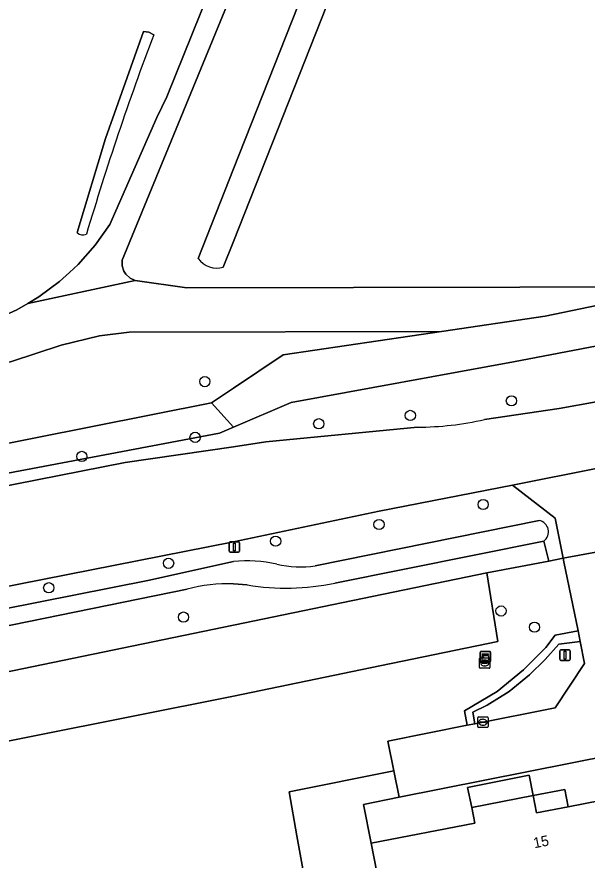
# Model space of a CAD drawing. Extents: x 160203 to 161530, y 379528 to 381797.
# Drawn here: x 160979.3 to 161033.8, y 379917 to 379997.6 of the extents above; entities that cross this region are included whole.
import ezdxf

# ---------------------------------------------------------------- set-up
doc = ezdxf.new("R2010")
doc.units = 0
for name, color, linetype in [('IMGEO_Boom', 7, 'Continuous'), ('IMGEO_Grasland_overig', 7, 'Continuous'), ('IMGEO_Groenvoorziening', 7, 'Continuous'), ('IMGEO_Hek', 7, 'Continuous'), ('IMGEO_Kast', 7, 'Continuous'), ('IMGEO_Kolk', 7, 'Continuous'), ('IMGEO_Lichtmast', 7, 'Continuous'), ('IMGEO_Loofbos', 7, 'Continuous'), ('IMGEO_Pand', 7, 'Continuous'), ('IMGEO_Pand_nummerreeks', 7, 'Continuous'), ('IMGEO_Rijbaan_lokaal_open', 7, 'Continuous'), ('IMGEO_Rioolput', 7, 'Continuous'), ('IMGEO_Voetpad_onverhard', 7, 'Continuous'), ('IMGEO_Voetpad_open', 7, 'Continuous'), ('IMGEO_Waterloop', 7, 'Continuous')]:
    doc.layers.add(name, color=color, linetype=linetype)

msp = doc.modelspace()

# ---------------------------------------------------------------- linework, layer by layer
at = {"layer": 'IMGEO_Boom'}
for centre in [(160997.258, 379962.718), (161026.554, 379960.88), (161016.895, 379959.487), (161008.142, 379958.692), (160996.323, 379957.392), (160985.503, 379955.574), (161023.86, 379950.978), (161013.905, 379949.071), (161004.021, 379947.471), (160993.789, 379945.357), (160982.341, 379943.021), (161025.562, 379940.803), (160995.214, 379940.22), (161028.765, 379939.255)]:
    msp.add_circle(centre, 0.489, dxfattribs=at)
at = {"layer": 'IMGEO_Grasland_overig'}
msp.add_lwpolyline([(161008.006, 379908.641), (161006.059, 379919.315), (161005.317, 379923.52), (161015.307, 379925.53), (161014.737, 379928.361), (161022.338, 379929.878), (161022.088, 379931.253), (161025.189, 379933.097), (161027.702, 379935.192), (161029.839, 379937.308), (161030.74, 379938.502), (161032.921, 379938.901), (161031.58, 379945.502), (161031.511, 379945.843), (161030.126, 379945.579), (161024.194, 379944.451), (161025.245, 379937.898), (161013.069, 379935.373), (161000, 379932.662), (160951.544, 379923.025), (160959.272, 379883.804)], dxfattribs=at)
at = {"layer": 'IMGEO_Groenvoorziening'}
for points in [[(161029.658, 379947.483), (161030.126, 379945.579), (161031.511, 379945.843), (161030.736, 379949.662), (161026.674, 379952.839), (161013.911, 379950.345), (161000, 379947.411), (160936.325, 379934.86), (160930.729, 379933.941), (160927.405, 379933.308)], [(161007.816, 379945.111), (161029.198, 379949.449)], [(161000, 379939.454), (161011.409, 379941.81), (161024.194, 379944.451), (161030.126, 379945.579), (161029.658, 379947.483), (161009.68, 379943.467)], [(160939.993, 379933.455), (160991.806, 379943.722), (161000, 379945.518)], [(161001.31, 379943.287), (161000, 379943.392)], [(160995.56, 379942.876), (160940.767, 379931.705), (160943.379, 379927.759), (161000, 379939.454)]]:
    msp.add_lwpolyline(points, dxfattribs=at)
for points in [[(161033.129, 379937.878), (161032.921, 379938.901), (161030.74, 379938.502), (161029.839, 379937.308), (161027.702, 379935.192), (161025.189, 379933.097), (161022.088, 379931.253), (161022.338, 379929.878), (161023.071, 379930.024), (161022.863, 379931.128), (161024.225, 379931.798), (161026.341, 379933.097), (161028.289, 379934.71), (161029.777, 379936.156), (161031.096, 379937.622)], [(161033.555, 379935.783), (161033.129, 379937.878), (161031.096, 379937.622), (161029.777, 379936.156), (161028.289, 379934.71), (161026.341, 379933.097), (161024.225, 379931.798), (161022.863, 379931.128), (161023.071, 379930.024), (161030.744, 379931.555)]]:
    msp.add_lwpolyline(points, close=True, dxfattribs=at)
for centre, radius, start, end in [((161029.003, 379948.367), 1.1, 306.54814, 79.78991), ((161001.34, 379933.014), 12.576, 77.15642, 96.11878), ((161006.447, 379955.76), 10.737, 257.57086, 277.32572), ((160999.474, 379928.555), 14.846, 87.97087, 105.28706), ((161005.018, 379965.579), 22.598, 260.55704, 281.90691)]:
    msp.add_arc(centre, radius, start, end, dxfattribs=at)
at = {"layer": 'IMGEO_Hek'}
for points in [[(161031.511, 379945.843), (161030.126, 379945.579)], [(161030.126, 379945.579), (161024.194, 379944.451)], [(161024.194, 379944.451), (161025.245, 379937.898), (161013.069, 379935.373)], [(161013.069, 379935.373), (161000, 379932.662)], [(161000, 379932.662), (160951.544, 379923.025), (160959.272, 379883.804)]]:
    msp.add_lwpolyline(points, dxfattribs=at)
at = {"layer": 'IMGEO_Kast'}
for p, q in [((161023.644, 379936.933), (161024.485, 379936.933)), ((161024.485, 379936.933), (161023.644, 379936.933)), ((161024.569, 379936.858), (161024.569, 379936.017)), ((161024.569, 379936.017), (161024.569, 379936.858)), ((161023.569, 379936.008), (161023.569, 379936.849)), ((161023.569, 379936.849), (161023.569, 379936.008)), ((161024.494, 379935.933), (161023.653, 379935.933)), ((161023.653, 379935.933), (161024.494, 379935.933))]:
    msp.add_line(p, q, dxfattribs=at)
for points in [[(161023.764, 379936.723), (161024.364, 379936.723), (161024.364, 379936.638), (161023.764, 379936.638), (161023.764, 379936.723)], [(161023.764, 379936.548), (161024.364, 379936.548), (161024.364, 379936.059), (161023.764, 379936.059), (161023.764, 379936.548)]]:
    msp.add_lwpolyline(points, dxfattribs=at)
msp.add_circle((161023.848, 379936.397), 0.0377, dxfattribs=at)
for centre, start, end in [((161023.647, 379936.855), 92.4484, 184.28452), ((161023.647, 379936.855), 92.4484, 184.28452), ((161024.491, 379936.855), 2.4484, 94.28452), ((161024.491, 379936.855), 2.4484, 94.28452), ((161023.647, 379936.011), 182.4484, 274.28452), ((161023.647, 379936.011), 182.4484, 274.28452), ((161024.491, 379936.011), 272.4484, 4.28452), ((161024.491, 379936.011), 272.4484, 4.28452)]:
    msp.add_arc(centre, 0.0779, start, end, dxfattribs=at)
at = {"layer": 'IMGEO_Kolk'}
for p, q in [((161023.337, 379929.75), (161023.337, 379930.602)), ((161023.412, 379930.676), (161024.264, 379930.676)), ((161023.825, 379930.456), (161023.85, 379930.456)), ((161024.338, 379930.602), (161024.338, 379929.75)), ((161024.264, 379929.676), (161023.412, 379929.676)), ((161023.596, 379930.17), (161023.596, 379930.182)), ((161024.034, 379930.133), (161023.636, 379930.133)), ((161023.639, 379930.219), (161024.037, 379930.219)), ((161023.848, 379929.896), (161023.823, 379929.896)), ((161024.08, 379930.182), (161024.08, 379930.17))]:
    msp.add_line(p, q, dxfattribs=at)
for points in [[(161023.337, 379929.75), (161023.337, 379930.602)], [(161023.412, 379930.676), (161024.264, 379930.676)], [(161024.338, 379930.602), (161024.338, 379929.75)], [(161024.264, 379929.676), (161023.412, 379929.676)]]:
    msp.add_lwpolyline(points, dxfattribs=at)
for centre, radius, start, end in [((161023.414, 379930.6), 0.0765, 91.55205, 178.44795), ((161023.414, 379930.6), 0.0765, 91.55205, 178.44795), ((161024.262, 379930.6), 0.0765, 1.55205, 88.44795), ((161024.262, 379930.6), 0.0765, 1.55205, 88.44795), ((161023.414, 379929.752), 0.0765, 181.55205, 268.44795), ((161023.414, 379929.752), 0.0765, 181.55205, 268.44795), ((161023.636, 379930.179), 0.0403, 85.87752, 175.75265), ((161023.633, 379930.169), 0.0366, 178.93798, 274.71019), ((161024.037, 379930.176), 0.043, 264.86636, 352.45326), ((161024.041, 379930.181), 0.0386, 1.73085, 96.63898), ((161024.262, 379929.752), 0.0765, 271.55205, 358.44795), ((161024.262, 379929.752), 0.0765, 271.55205, 358.44795)]:
    msp.add_arc(centre, radius, start, end, dxfattribs=at)
for centre, major_axis, ratio, start_param, end_param in [((161023.824, 379930.176), (-0.387, 0.002), 0.722429, 4.712389, 7.853982), ((161023.849, 379930.176), (-0.39, 0.002), 0.717154, 1.570796, 4.712389)]:
    msp.add_ellipse(centre, major_axis=major_axis, ratio=ratio, start_param=start_param, end_param=end_param, dxfattribs=at)
at = {"layer": 'IMGEO_Lichtmast'}
for p, q in [((160999.689, 379947.418), (161000.479, 379947.418)), ((161000.479, 379947.418), (160999.689, 379947.418)), ((160999.589, 379946.518), (160999.589, 379947.318)), ((160999.589, 379947.318), (160999.589, 379946.518)), ((161000.579, 379947.318), (161000.579, 379946.518)), ((161000.579, 379946.518), (161000.579, 379947.318)), ((161000.479, 379946.418), (160999.689, 379946.418)), ((160999.689, 379946.418), (161000.479, 379946.418)), ((161031.193, 379936.186), (161031.193, 379936.986)), ((161031.193, 379936.986), (161031.193, 379936.186)), ((161031.293, 379937.086), (161032.083, 379937.086)), ((161032.083, 379937.086), (161031.293, 379937.086)), ((161032.183, 379936.986), (161032.183, 379936.186)), ((161032.183, 379936.186), (161032.183, 379936.986)), ((161032.083, 379936.086), (161031.293, 379936.086)), ((161031.293, 379936.086), (161032.083, 379936.086))]:
    msp.add_line(p, q, dxfattribs=at)
for points in [[(161000.009, 379947.293), (161000.159, 379947.293), (161000.159, 379946.543), (161000.009, 379946.543), (161000.009, 379947.293)], [(161031.613, 379936.961), (161031.763, 379936.961), (161031.763, 379936.211), (161031.613, 379936.211), (161031.613, 379936.961)]]:
    msp.add_lwpolyline(points, dxfattribs=at)
for centre, start, end in [((160999.689, 379947.318), 90, 180), ((160999.689, 379947.318), 90, 180), ((161000.479, 379947.318), 0, 90), ((161000.479, 379947.318), 360, 90), ((160999.689, 379946.518), 180, 270), ((160999.689, 379946.518), 180, 270), ((161000.479, 379946.518), 270, 0), ((161000.479, 379946.518), 270, 0), ((161031.293, 379936.986), 90, 180), ((161031.293, 379936.986), 90, 180), ((161032.083, 379936.986), 0, 90), ((161032.083, 379936.986), 360, 90), ((161031.293, 379936.186), 180, 270), ((161031.293, 379936.186), 180, 270), ((161032.083, 379936.186), 270, 0), ((161032.083, 379936.186), 270, 0)]:
    msp.add_arc(centre, 0.1, start, end, dxfattribs=at)
at = {"layer": 'IMGEO_Loofbos'}
for points in [[(161052.225, 380030.051), (161019.281, 380024.896), (161017.421, 380024.586), (161017.24, 380024.558), (161016.059, 380030.822), (161013.831, 380030.846), (161014.708, 380026.37), (161016.833, 380018.757), (161009.428, 380000), (161000, 379976.12), (160999.016, 379973.646)], [(160910.327, 380007.409), (160920.602, 379955.987), (160921, 379955.813), (160922.449, 379955.516), (160923.188, 379955.482), (160935.494, 379958.213), (160972.092, 379967.237), (160974.767, 379967.81), (160977.079, 379968.582), (160979.298, 379969.591), (160980.332, 379970.199), (160981.399, 379970.826), (160983.359, 379972.274), (160984.32, 379973.153), (160985.158, 379973.92), (160986.774, 379975.744), (160988.191, 379977.727), (160992.684, 379987.962), (160993.627, 379989.939), (160997.664, 379999.984)], [(160999.915, 380000.009), (160989.365, 379974.323), (160989.363, 379973.786), (160989.527, 379973.275), (160989.721, 379972.973), (160990.119, 379972.613), (160990.608, 379972.392), (160995.525, 379971.689), (161043.296, 379971.789)], [(160996.624, 379974.475), (161000, 379983.055), (161006.691, 380000)], [(160987.767, 379985.934), (160991.408, 379996.16), (160991.919, 379996.12), (160992.366, 379995.868)], [(160985.041, 379976.957), (160987.767, 379985.934)], [(161093.454, 379977.21), (161081.741, 379975.129), (161026.757, 379964.623), (161005.514, 379960.734), (161000, 379958.372), (160998.654, 379957.795), (160935.592, 379945.881), (160935.239, 379948.227), (160922.706, 379945.785), (160921.668, 379948.198), (160919.01, 379947.114), (160919.54, 379945.851)], [(161023.99, 379959.09), (161031.108, 379960.14), (161038.188, 379961.422), (161094.262, 379972.527)], [(160926.483, 379942.53), (160935.112, 379944.265), (160989.654, 379954.98), (160999.998, 379956.482), (161003.088, 379956.98), (161017.577, 379958.366)]]:
    msp.add_lwpolyline(points, dxfattribs=at)
for points in [[(160997.906, 379960.687), (161000, 379962.09), (161004.745, 379965.268), (161019.862, 379967.505), (160990.026, 379967.436), (160987.186, 379967.088), (160983.541, 379966.218), (160978.788, 379964.646), (160970.004, 379962.58), (160935.992, 379955.526), (160925.518, 379952.646), (160924.211, 379951.846), (160923.099, 379950.792), (160922.23, 379949.53), (160921.668, 379948.198), (160922.706, 379945.785), (160935.239, 379948.227)], [(160952.452, 379881.869), (160959.428, 379883.014), (160959.272, 379883.804), (160951.544, 379923.025), (161000, 379932.662), (161013.069, 379935.373), (161025.245, 379937.898), (161024.194, 379944.451), (161011.409, 379941.81), (161000, 379939.454), (160943.379, 379927.759)]]:
    msp.add_lwpolyline(points, close=True, dxfattribs=at)
for centre, radius, start, end in [((161257.812, 379895.769), 283.692, 159.33872, 163.40228), ((160985.593, 379977.493), 0.769, 224.14196, 296.78874), ((160998.413, 379975.771), 2.209, 215.92327, 285.84697), ((161017.4, 379988.702), 30.336, 270.33511, 282.54724)]:
    msp.add_arc(centre, radius, start, end, dxfattribs=at)
at = {"layer": 'IMGEO_Pand'}
msp.add_lwpolyline([(161046.896, 379912.321), (161044.514, 379924.54), (161031.976, 379922.096), (161028.959, 379921.508), (161028.637, 379923.159), (161022.767, 379922.015), (161023.054, 379920.543), (161013.14, 379918.61), (161015.016, 379908.99), (161011.092, 379908.224), (161011.112, 379908.12), (161011.931, 379903.919), (161012.674, 379900.106), (161016.6, 379900.871), (161017.231, 379897.34), (161019.464, 379897.771), (161029.029, 379899.615), (161028.111, 379904.521), (161034.944, 379905.853), (161035.16, 379905.895), (161034.758, 379907.958), (161047.271, 379910.397)], close=True, dxfattribs=at)
at = {"layer": 'IMGEO_Rijbaan_lokaal_open'}
for points in [[(161044.221, 379956.334), (161108.127, 379968.844), (161108.111, 379969.144), (161118.172, 379970.493), (161117.701, 379976.481), (161107.96, 379975.052), (161107.822, 379975.214), (161105.071, 379974.669), (161094.262, 379972.527), (161038.188, 379961.422), (161031.108, 379960.14), (161023.99, 379959.09)], [(161017.577, 379958.366), (161003.088, 379956.98), (160999.998, 379956.482), (160989.654, 379954.98), (160935.112, 379944.265), (160926.483, 379942.53)], [(160927.405, 379933.308), (160930.729, 379933.941), (160936.325, 379934.86), (161000, 379947.411), (161013.911, 379950.345), (161026.674, 379952.839), (161034.962, 379954.474), (161044.221, 379956.334)]]:
    msp.add_lwpolyline(points, dxfattribs=at)
for points in [[(161034.962, 379954.474), (161026.674, 379952.839), (161030.736, 379949.662), (161031.511, 379945.843), (161036.526, 379946.773)], [(161037.21, 379943.405), (161036.526, 379946.773), (161031.511, 379945.843), (161031.58, 379945.502), (161032.921, 379938.901), (161033.129, 379937.878), (161033.555, 379935.783), (161030.744, 379931.555), (161023.071, 379930.024), (161022.338, 379929.878), (161014.737, 379928.361), (161015.307, 379925.53), (161015.815, 379923.004), (161040.379, 379927.872), (161038.943, 379934.911)]]:
    msp.add_lwpolyline(points, close=True, dxfattribs=at)
msp.add_arc((161017.4, 379988.702), 30.336, 270.33511, 282.54724, dxfattribs=at)
at = {"layer": 'IMGEO_Rioolput'}
for p, q in [((161023.506, 379935.404), (161023.506, 379936.256)), ((161023.581, 379936.33), (161024.433, 379936.33)), ((161023.994, 379936.11), (161024.019, 379936.11)), ((161024.507, 379936.256), (161024.507, 379935.404)), ((161024.433, 379935.33), (161023.581, 379935.33)), ((161023.765, 379935.824), (161023.765, 379935.836)), ((161024.203, 379935.787), (161023.805, 379935.787)), ((161023.808, 379935.873), (161024.206, 379935.873)), ((161024.017, 379935.55), (161023.992, 379935.55)), ((161024.249, 379935.836), (161024.249, 379935.824))]:
    msp.add_line(p, q, dxfattribs=at)
for points in [[(161023.506, 379935.404), (161023.506, 379936.256)], [(161023.581, 379936.33), (161024.433, 379936.33)], [(161024.507, 379936.256), (161024.507, 379935.404)], [(161024.433, 379935.33), (161023.581, 379935.33)]]:
    msp.add_lwpolyline(points, dxfattribs=at)
for centre, radius, start, end in [((161023.583, 379936.254), 0.0765, 91.55205, 178.44795), ((161023.583, 379936.254), 0.0765, 91.55205, 178.44795), ((161024.431, 379936.254), 0.0765, 1.55205, 88.44795), ((161024.431, 379936.254), 0.0765, 1.55205, 88.44795), ((161023.583, 379935.406), 0.0765, 181.55205, 268.44795), ((161023.583, 379935.406), 0.0765, 181.55205, 268.44795), ((161023.805, 379935.833), 0.0403, 85.87752, 175.75265), ((161023.802, 379935.823), 0.0366, 178.93798, 274.71019), ((161024.206, 379935.83), 0.043, 264.86636, 352.45326), ((161024.21, 379935.835), 0.0386, 1.73085, 96.63898), ((161024.431, 379935.406), 0.0765, 271.55205, 358.44795), ((161024.431, 379935.406), 0.0765, 271.55205, 358.44795)]:
    msp.add_arc(centre, radius, start, end, dxfattribs=at)
for centre, major_axis, ratio, start_param, end_param in [((161023.993, 379935.83), (-0.387, 0.002), 0.722429, 4.712389, 7.853982), ((161024.018, 379935.83), (-0.39, 0.002), 0.717154, 1.570796, 4.712389)]:
    msp.add_ellipse(centre, major_axis=major_axis, ratio=ratio, start_param=start_param, end_param=end_param, dxfattribs=at)
at = {"layer": 'IMGEO_Voetpad_onverhard'}
for points in [[(160997.664, 379999.984), (160993.627, 379989.939), (160992.684, 379987.962), (160988.191, 379977.727), (160986.774, 379975.744), (160985.158, 379973.92), (160984.32, 379973.153), (160983.359, 379972.274), (160981.399, 379970.826), (160980.332, 379970.199), (160990.608, 379972.392), (160990.119, 379972.613), (160989.721, 379972.973), (160989.527, 379973.275), (160989.363, 379973.786), (160989.365, 379974.323), (160999.915, 380000.009)], [(160925.518, 379952.646), (160935.992, 379955.526), (160970.004, 379962.58), (160978.788, 379964.646), (160983.541, 379966.218), (160987.186, 379967.088), (160990.026, 379967.436), (161019.862, 379967.505), (161029.768, 379968.971), (161043.296, 379971.789), (160995.525, 379971.689), (160990.608, 379972.392), (160980.332, 379970.199), (160979.298, 379969.591), (160977.079, 379968.582), (160974.767, 379967.81), (160972.092, 379967.237), (160935.494, 379958.213), (160923.188, 379955.482)]]:
    msp.add_lwpolyline(points, dxfattribs=at)
at = {"layer": 'IMGEO_Voetpad_open'}
for points in [[(161040.379, 379927.872), (161015.815, 379923.004), (161012.435, 379922.324), (161013.14, 379918.61), (161023.054, 379920.543), (161022.767, 379922.015), (161022.371, 379923.937), (161028.249, 379925.107), (161028.637, 379923.159), (161031.654, 379923.747), (161031.976, 379922.096), (161044.514, 379924.54)], [(161015.016, 379908.99), (161013.14, 379918.61), (161012.435, 379922.324), (161015.815, 379923.004), (161015.307, 379925.53), (161005.317, 379923.52), (161006.059, 379919.315), (161008.006, 379908.641)]]:
    msp.add_lwpolyline(points, dxfattribs=at)
for points in [[(161022.767, 379922.015), (161028.637, 379923.159), (161028.249, 379925.107), (161022.371, 379923.937)], [(161031.654, 379923.747), (161028.637, 379923.159), (161028.959, 379921.508), (161031.976, 379922.096)]]:
    msp.add_lwpolyline(points, close=True, dxfattribs=at)
at = {"layer": 'IMGEO_Waterloop'}
for points in [[(160999.016, 379973.646), (161000, 379976.12), (161009.428, 380000), (161016.833, 380018.757), (161014.708, 380026.37), (161013.831, 380030.846), (161011.343, 380030.664), (161012.132, 380025.981), (161014.173, 380018.949), (161006.691, 380000), (161000, 379983.055), (160996.624, 379974.475)], [(160992.366, 379995.868), (160991.919, 379996.12), (160991.408, 379996.16), (160987.767, 379985.934), (160985.041, 379976.957)], [(161092.807, 379981.863), (161043.296, 379971.789), (161029.768, 379968.971), (161019.862, 379967.505), (161004.745, 379965.268), (161000, 379962.09), (160997.906, 379960.687), (161000, 379958.372), (161005.514, 379960.734), (161026.757, 379964.623), (161081.741, 379975.129)], [(161029.198, 379949.449), (161007.816, 379945.111)], [(161009.68, 379943.467), (161029.658, 379947.483)], [(161000, 379945.518), (160991.806, 379943.722), (160939.993, 379933.455)], [(161000, 379943.392), (161001.31, 379943.287)], [(160940.056, 379931.56), (160940.767, 379931.705), (160995.56, 379942.876)]]:
    msp.add_lwpolyline(points, dxfattribs=at)
msp.add_lwpolyline([(160998.654, 379957.795), (161000, 379958.372), (160997.906, 379960.687), (160935.239, 379948.227), (160935.592, 379945.881)], close=True, dxfattribs=at)
for centre, radius, start, end in [((161257.812, 379895.769), 283.692, 159.33872, 163.40228), ((160985.593, 379977.493), 0.769, 224.14196, 296.78874), ((160998.413, 379975.771), 2.209, 215.92327, 285.84697), ((161029.003, 379948.367), 1.1, 306.54814, 79.78991), ((161001.34, 379933.014), 12.576, 77.15642, 96.11878), ((161006.447, 379955.76), 10.737, 257.57086, 277.32572), ((160999.474, 379928.555), 14.846, 87.97087, 105.28706), ((161005.018, 379965.579), 22.598, 260.55704, 281.90691)]:
    msp.add_arc(centre, radius, start, end, dxfattribs=at)

# ---------------------------------------------------------------- texts
at = {"layer": 'IMGEO_Pand_nummerreeks'}
msp.add_text('15', height=1, rotation=11.02986, dxfattribs=at).set_placement((161028.75, 379918.126))

doc.saveas('drawing.dxf')
